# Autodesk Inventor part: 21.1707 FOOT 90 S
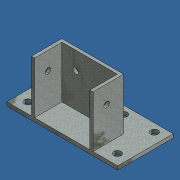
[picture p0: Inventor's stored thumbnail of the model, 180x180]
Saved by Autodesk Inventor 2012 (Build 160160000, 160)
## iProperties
Created: 2007-04
Part Number: 21.1707 FOOT 90 S
Material: Steel
Document SubType Name: Modeling
Designer: Andy Moles
Mass: 1155.57 g
Surface Area: 608.125 cm^2
Volume: 147.206 cm^3
Density: 7.85 g/cm^3
Author: Andy Moles
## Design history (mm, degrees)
sketch "Sketch1"
  geometry: L1 (90, -44.5)-(90, 45.5); L2 (90, 45.5)-(-90, 45.5); L3 (-90, 45.5)-(-90, -44.5); L4 (45, -44.5)-(45, 0); L5 (45, 0)-(-45, 0); L6 (-45, 0)-(-45, -44.5); L7 (-90, -44.5)-(-45, -44.5); L8 (45, -44.5)-(90, -44.5); L9 (-45, -44.5)-(45, -44.5); C1 r 6 at (-72.5, -27.5); C2 r 6 at (-72.5, 32.5); C3 r 6 at (-22.5, 32.5); C4 r 6 at (22.5, 32.5); C5 r 6 at (72.5, 32.5); C6 r 6 at (72.5, -27.5); 2 further points
  constraints: 18 end point, 6 centre point, 4 horizontal alignment, 4 parallel, 3 collinear, 3 horizontal, 2 perpendicular, 2 vertical alignment, 1 coincident, 1 midpoint, 1 vertical
  dimensions: "d0" = 180 distance of L1.end L2.end; "d1" = 90 distance of L2.end L3.end; "d2" = 90 distance of L4.end L5.end; "d3" = 44.5 distance of L5.end L6.end; "d4" = 12 diameter of C1; "d5" = 12 diameter of C2; "d6" = 12 diameter of C3; "d7" = 12 diameter of C4; "d8" = 12 diameter of C5; "d9" = 12 diameter of C6; "d11" = 17.5 distance from line of C2.centre L3; "d12" = 17.5 distance from line of C5.centre L1; "d13" = 17 distance from line of C1.centre L7; "d14" = 50 distance of C3.centre C2.centre; "d34" = 50 distance of C4.centre C5.centre; "d37" = 60 distance of C2.centre C1.centre; "d38" = 145 distance of C2.centre C5.centre (derived); "d39" = 45 distance of C3.centre C4.centre (derived)
extrude "Extrusion1" new body sketch "Sketch1" distance "d16" = 6; taper "d17" = 0 deg
sketch "Sketch2"
  geometry: L1 (-45, -44.5)-(-90, -44.5) reference; L2 (-45, 0)-(-45, -44.5) reference; L3 (45, 0)-(-45, 0) reference; L4 (90, -44.5)-(45, -44.5) reference; L5 (45, -44.5)-(45, 0); L6 (45, 0)-(-45, 0); L7 (-45, 0)-(-45, -44.5); L8 (-50, -44.5)-(-50, 5); L9 (-50, 5)-(50, 5); L10 (50, 5)-(50, -44.5); L11 (-50, -44.5)-(-45, -44.5); L12 (45, -44.5)-(50, -44.5); 1 further point
  constraints: 16 end point, 2 parallel, 2 point on line, 1 collinear
extrude "Extrusion2" join sketch "Sketch2" distance "d19" = 84; taper "d20" = 0 deg
sketch "Sketch3"
  geometry: L1 (84, 49.5)-(84, 0) reference; L2 (90, 44.5)-(0, 44.5) reference; C1 r 4.5 at (29, 22)
  constraints: 1 centre point
  dimensions: "d21" = 9 diameter of C1; "d22" = 22.5 distance from line of L2 C1.centre; "d23" = 55 distance from line of C1.centre L1
extrude "Extrusion3" cut sketch "Sketch3" stored distance "d24" = 83.6; taper "d25" = 0 deg
sketch "Sketch4"
  geometry: L1 (0, 84)-(100, 84) reference; L2 (95, 90)-(95, 0) reference; L3 (5, 90)-(5, 0) reference; C1 r 4.5 at (72.5, 29); C2 r 4.5 at (27.5, 29); 1 further point
  constraints: 2 centre point
  dimensions: "d26" = 9 diameter of C1; "d27" = 9 diameter of C2; "d28" = 55 distance from line of C1.centre L1; "d29" = 55 distance from line of L1 C2.centre; "d30" = 22.5 distance from line of C1.centre L2; "d31" = 22.5 distance from line of L3 C2.centre
extrude "Extrusion4" cut sketch "Sketch4" distance "d32" = 83.6; taper "d33" = 0 deg
sketch "Sketch5"
  geometry: L1 (-45, -44.5)-(-45, 0) reference; L2 (-45, 0)-(45, 0) reference; L3 (45, 0)-(45, -44.5) reference; L4 (45, -44.5)-(-45, -44.5); 1 further point
  constraints: 2 end point, 1 perpendicular
extrude "Extrusion5" join sketch "Sketch5" distance "d35" = 6; taper "d36" = 0 deg
body "Solid1"
